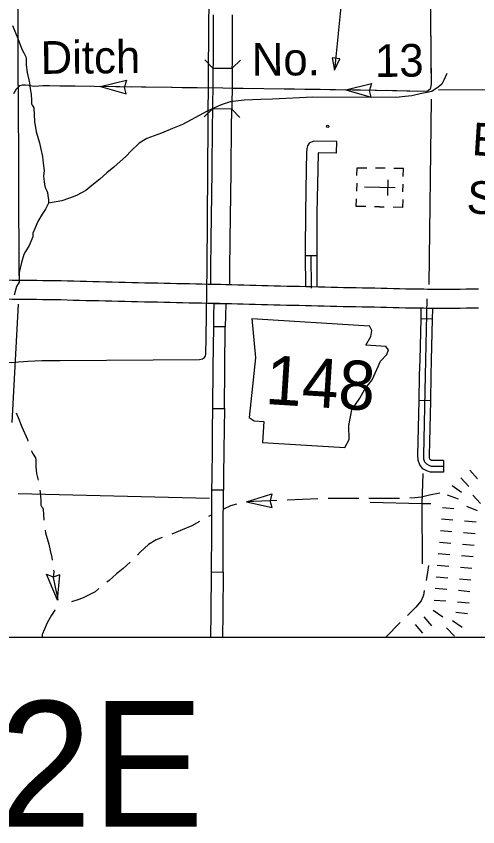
# Model space of a CAD drawing. Extents: x 1366406 to 1373462, y 376856 to 381998.
# Drawn here: x 1369525.2 to 1369621.8, y 379441 to 379610.7 of the extents above; entities that cross this region are included whole.
import ezdxf

# ---------------------------------------------------------------- set-up
doc = ezdxf.new("R2010")
doc.units = 0
for name, color, linetype in [('10', 7, 'Continuous'), ('21', 7, 'Continuous'), ('29', 7, 'Continuous'), ('31', 7, 'Continuous'), ('32', 7, 'Continuous'), ('37', 7, 'Continuous'), ('4', 7, 'Continuous'), ('41', 7, 'Continuous'), ('43', 7, 'Continuous'), ('45', 7, 'Continuous'), ('46', 7, 'Continuous'), ('5', 7, 'Continuous'), ('57', 7, 'Continuous'), ('Default', 7, 'Continuous'), ('R_No Plot', 7, 'Continuous')]:
    doc.layers.add(name, color=color, linetype=linetype)

msp = doc.modelspace()

# ---------------------------------------------------------------- linework, layer by layer
at = {"layer": '10'}
for points in [[(1369566.45, 379610.97), (1369566.45, 379609.71), (1369566.45, 379608.44), (1369566.44, 379607.16), (1369566.44, 379605.88), (1369566.43, 379604.6), (1369566.43, 379603.33), (1369566.43, 379602.06), (1369566.42, 379600.81), (1369566.41, 379599.82), (1369570.46, 379599.78)], [(1369570.46, 379599.78), (1369570.47, 379600.78), (1369570.48, 379602.05), (1369570.48, 379603.32), (1369570.48, 379604.59), (1369570.49, 379605.87), (1369570.49, 379607.15), (1369570.5, 379608.42), (1369570.5, 379609.69), (1369570.5, 379610.97)], [(1369566.41, 379599.82), (1369566.4, 379598.32), (1369566.38, 379597.09)], [(1369570.46, 379599.78), (1369570.43, 379597.05)], [(1369566.38, 379597.09), (1369566.37, 379595.87), (1369566.36, 379594.67), (1369566.34, 379593.47), (1369566.32, 379592.27), (1369566.31, 379591.28)], [(1369570.43, 379597.05), (1369570.42, 379595.83), (1369570.41, 379594.61), (1369570.39, 379593.41), (1369570.37, 379592.21), (1369570.36, 379591.21)], [(1369566.31, 379591.28), (1369566.3, 379591.07), (1369566.28, 379589.85), (1369566.27, 379588.63), (1369566.26, 379587.41), (1369566.25, 379586.19), (1369566.23, 379584.96), (1369566.21, 379583.72), (1369566.2, 379582.47), (1369566.19, 379581.23), (1369566.18, 379579.99), (1369566.16, 379578.76), (1369566.15, 379577.53), (1369566.14, 379576.33), (1369566.13, 379575.14), (1369566.11, 379573.96), (1369566.1, 379572.79), (1369566.08, 379571.61), (1369566.06, 379570.43), (1369566.04, 379569.25), (1369566.02, 379568.07), (1369566, 379566.89), (1369565.98, 379565.72), (1369565.97, 379564.57), (1369565.96, 379563.44), (1369565.95, 379562.33), (1369565.93, 379561.24), (1369565.92, 379560.18), (1369565.87, 379554.59), (1369569.92, 379554.5)], [(1369569.92, 379554.5), (1369569.97, 379560.14), (1369569.98, 379561.19), (1369570, 379562.28), (1369570, 379563.39), (1369570.02, 379564.52), (1369570.03, 379565.67), (1369570.05, 379566.83), (1369570.07, 379568), (1369570.09, 379569.18), (1369570.11, 379570.37), (1369570.13, 379571.55), (1369570.15, 379572.73), (1369570.16, 379573.91), (1369570.18, 379575.09), (1369570.19, 379576.29), (1369570.2, 379577.49), (1369570.21, 379578.72), (1369570.23, 379579.95), (1369570.24, 379581.2), (1369570.25, 379582.43), (1369570.26, 379583.66), (1369570.28, 379584.9), (1369570.3, 379586.13), (1369570.31, 379587.37), (1369570.32, 379588.6), (1369570.33, 379589.81), (1369570.35, 379591.01), (1369570.36, 379591.21), (1369566.31, 379591.28)], [(1369533.29, 379551.28), (1369532, 379551.3), (1369530.73, 379551.32), (1369529.45, 379551.33), (1369528.18, 379551.35), (1369526.9, 379551.36), (1369525.61, 379551.37), (1369524.33, 379551.39), (1369523.06, 379551.4), (1369521.78, 379551.41), (1369520.49, 379551.43), (1369520.44, 379551.43), (1369520.56, 379555.48)], [(1369520.53, 379555.48), (1369520.56, 379555.48), (1369521.82, 379555.46), (1369523.09, 379555.45), (1369524.38, 379555.44), (1369525.66, 379555.42), (1369526.94, 379555.41), (1369528.22, 379555.4), (1369529.5, 379555.38), (1369530.79, 379555.37), (1369532.07, 379555.35), (1369533.35, 379555.33)], [(1369533.35, 379555.33), (1369534.65, 379555.31), (1369535.95, 379555.27), (1369537.25, 379555.24), (1369538.57, 379555.21), (1369539.9, 379555.17), (1369541.24, 379555.14), (1369542.59, 379555.12), (1369543.95, 379555.08), (1369545.32, 379555.05), (1369546.69, 379555.01), (1369548.05, 379554.97), (1369549.41, 379554.94), (1369550.78, 379554.91), (1369552.14, 379554.88), (1369553.5, 379554.86), (1369554.86, 379554.83), (1369556.2, 379554.8), (1369557.54, 379554.77), (1369558.87, 379554.73), (1369560.19, 379554.71), (1369561.5, 379554.68), (1369562.8, 379554.65), (1369564.1, 379554.63), (1369565.37, 379554.6), (1369566.63, 379554.57), (1369567.84, 379554.55)], [(1369567.85, 379554.55), (1369568.05, 379554.54), (1369569.13, 379554.51), (1369570.38, 379554.48), (1369571.63, 379554.45), (1369572.88, 379554.42), (1369574.13, 379554.38), (1369575.38, 379554.35), (1369576.65, 379554.31), (1369577.93, 379554.28), (1369579.24, 379554.25), (1369580.56, 379554.22), (1369581.87, 379554.19), (1369583.19, 379554.17), (1369584.51, 379554.14), (1369585.84, 379554.12), (1369587.18, 379554.09), (1369588.51, 379554.05), (1369589.83, 379554.01), (1369591.15, 379553.97), (1369592.45, 379553.93), (1369593.76, 379553.9), (1369595.06, 379553.88), (1369596.37, 379553.86), (1369597.68, 379553.84), (1369599, 379553.82), (1369600.31, 379553.78), (1369601.61, 379553.75), (1369602.91, 379553.72), (1369604.21, 379553.69), (1369605.49, 379553.65), (1369606.76, 379553.63), (1369608.03, 379553.61), (1369609.29, 379553.58), (1369610.57, 379553.57), (1369611.3, 379553.54), (1369613.06, 379553.56), (1369614.34, 379553.55), (1369615.61, 379553.55), (1369616.89, 379553.56), (1369618.17, 379553.56), (1369619.45, 379553.57), (1369620.73, 379553.57), (1369622.01, 379553.58)], [(1369567.76, 379550.5), (1369566.54, 379550.52), (1369565.28, 379550.55), (1369564.01, 379550.58), (1369562.72, 379550.6), (1369561.42, 379550.63), (1369560.1, 379550.66), (1369558.77, 379550.69), (1369557.44, 379550.72), (1369556.11, 379550.75), (1369554.77, 379550.78), (1369553.42, 379550.81), (1369552.06, 379550.84), (1369550.69, 379550.86), (1369549.32, 379550.89), (1369547.95, 379550.92), (1369546.58, 379550.96), (1369545.21, 379551), (1369543.85, 379551.03), (1369542.5, 379551.07), (1369541.15, 379551.09), (1369539.8, 379551.12), (1369538.46, 379551.16), (1369537.15, 379551.19), (1369535.85, 379551.23), (1369534.57, 379551.26), (1369533.29, 379551.28)], [(1369622.02, 379549.53), (1369620.74, 379549.52), (1369619.47, 379549.52), (1369618.18, 379549.51), (1369616.9, 379549.51), (1369615.62, 379549.5), (1369614.34, 379549.5), (1369613.07, 379549.51), (1369611.25, 379549.49), (1369610.48, 379549.52), (1369609.23, 379549.53), (1369607.96, 379549.56), (1369606.68, 379549.58), (1369605.39, 379549.61), (1369604.1, 379549.64), (1369602.82, 379549.67), (1369601.52, 379549.7), (1369600.21, 379549.73), (1369598.91, 379549.77), (1369597.62, 379549.79), (1369596.31, 379549.81), (1369595, 379549.83), (1369593.68, 379549.85), (1369592.35, 379549.88), (1369591.03, 379549.92), (1369589.7, 379549.96), (1369588.39, 379550), (1369587.07, 379550.04), (1369585.76, 379550.07), (1369584.44, 379550.09), (1369583.12, 379550.12), (1369581.79, 379550.14), (1369580.46, 379550.17), (1369579.14, 379550.2), (1369577.84, 379550.23), (1369576.54, 379550.26), (1369575.27, 379550.3), (1369574.01, 379550.33), (1369572.76, 379550.37), (1369571.52, 379550.4), (1369570.28, 379550.44), (1369569.02, 379550.47), (1369567.94, 379550.49), (1369567.75, 379550.5)]]:
    msp.add_lwpolyline(points, dxfattribs=at)
at = {"layer": '21'}
for p, q in [((1369574.57, 379547.4), (1369575.29, 379539.12)), ((1369599.68, 379544.86), (1369599.17, 379545.84)), ((1369599.46, 379543.64), (1369599.68, 379544.86)), ((1369598.39, 379541.79), (1369599.46, 379543.64)), ((1369602.63, 379541.52), (1369598.39, 379541.79)), ((1369603.13, 379540.8), (1369602.63, 379541.52)), ((1369602.8, 379539.86), (1369603.13, 379540.8)), ((1369575.29, 379539.12), (1369573.96, 379526.7)), ((1369601.47, 379538.44), (1369602.8, 379539.86)), ((1369600.68, 379536.7), (1369601.47, 379538.44)), ((1369599.72, 379534.56), (1369600.68, 379536.7)), ((1369598.22, 379532.6), (1369599.72, 379534.56)), ((1369597.14, 379530.74), (1369598.22, 379532.6)), ((1369595.48, 379528.24), (1369597.14, 379530.74)), ((1369594.86, 379524.98), (1369595.48, 379528.24)), ((1369573.96, 379526.7), (1369575.01, 379525.95)), ((1369575.01, 379525.95), (1369577.06, 379525.82)), ((1369577.06, 379525.82), (1369576.79, 379521.45)), ((1369594.95, 379522.09), (1369594.86, 379524.98)), ((1369594.02, 379520.37), (1369594.95, 379522.09)), ((1369576.79, 379521.45), (1369594.02, 379520.37))]:
    msp.add_line(p, q, dxfattribs=at)
msp.add_lwpolyline([(1369574.57, 379547.4), (1369599.17, 379545.84)], dxfattribs=at)
at = {"layer": '29'}
for p, q in [((1369620.15, 379515.64), (1369621.77, 379513.83)), ((1369618.33, 379514.02), (1369619.95, 379512.21)), ((1369616.5, 379512.43), (1369618.47, 379511.01)), ((1369615.46, 379510.47), (1369617.76, 379509.67)), ((1369620.82, 379510.44), (1369622.44, 379508.63)), ((1369614.44, 379507.85), (1369616.86, 379507.65)), ((1369619.49, 379508.13), (1369621.74, 379507.22)), ((1369614.23, 379505.44), (1369616.65, 379505.23)), ((1369619.07, 379505.01), (1369621.49, 379504.8)), ((1369614.01, 379503.02), (1369616.44, 379502.81)), ((1369614.01, 379503.02), (1369616.44, 379502.81)), ((1369618.86, 379502.59), (1369621.28, 379502.38)), ((1369618.86, 379502.59), (1369621.28, 379502.38)), ((1369613.8, 379500.6), (1369616.22, 379500.39)), ((1369618.64, 379500.17), (1369621.06, 379499.96)), ((1369613.58, 379498.18), (1369616.01, 379497.97)), ((1369618.43, 379497.75), (1369620.85, 379497.54)), ((1369613.37, 379495.76), (1369615.79, 379495.55)), ((1369613.37, 379495.76), (1369615.79, 379495.55)), ((1369618.21, 379495.33), (1369620.63, 379495.12)), ((1369618.21, 379495.33), (1369620.63, 379495.12)), ((1369613.16, 379493.34), (1369615.58, 379493.13)), ((1369618, 379492.91), (1369620.42, 379492.7)), ((1369612.94, 379490.92), (1369615.36, 379490.71)), ((1369617.78, 379490.49), (1369620.2, 379490.28)), ((1369612.75, 379488.45), (1369615.18, 379488.27)), ((1369612.75, 379488.45), (1369615.18, 379488.27)), ((1369617.6, 379488.08), (1369620.02, 379487.9)), ((1369617.6, 379488.08), (1369620.02, 379487.9)), ((1369612.53, 379486.36), (1369614.51, 379484.94)), ((1369610.56, 379484.93), (1369612.13, 379483.08)), ((1369610.56, 379484.93), (1369612.13, 379483.08)), ((1369617.24, 379485.9), (1369619.66, 379485.62)), ((1369608.71, 379483.35), (1369610.29, 379481.5)), ((1369616.58, 379484.18), (1369618.55, 379482.76)), ((1369615.32, 379482.66), (1369616.98, 379480.89))]:
    msp.add_line(p, q, dxfattribs=at)
at = {"layer": '31'}
for p, q in [((1369568.99, 379545.64), (1369566.56, 379545.66)), ((1369566.38, 379528.56), (1369568.81, 379528.53)), ((1369568.63, 379511.43), (1369566.2, 379511.45)), ((1369566.2, 379511.45), (1369566.2, 379511.45)), ((1369566.08, 379494.34), (1369568.51, 379494.32))]:
    msp.add_line(p, q, dxfattribs=at)
for points in [[(1369518.7, 379539.94), (1369519.99, 379539.34), (1369521.22, 379538.81), (1369522.12, 379538.54), (1369522.97, 379538.26), (1369524.13, 379538.19), (1369525.72, 379538.32), (1369526.71, 379538.39), (1369527.68, 379538.45), (1369530.55, 379538.61), (1369534.4, 379538.6), (1369563.62, 379538.83), (1369564.22, 379538.94), (1369564.66, 379539.22), (1369564.83, 379539.54), (1369564.88, 379539.85), (1369564.96, 379543.36), (1369565.19, 379558.13), (1369565.46, 379598.16), (1369565.57, 379608.14), (1369565.83, 379631.95), (1369565.94, 379634.8), (1369566.02, 379636.5)], [(1369566.56, 379545.66), (1369566.58, 379548), (1369566.68, 379550.52), (1369569.11, 379550.46)], [(1369569.11, 379550.46), (1369569.01, 379547.94), (1369568.99, 379545.64)], [(1369566.47, 379537.11), (1369566.56, 379545.66)], [(1369568.9, 379537.09), (1369568.99, 379545.64)], [(1369566.38, 379528.56), (1369566.47, 379537.11)], [(1369568.81, 379528.53), (1369568.9, 379537.09)], [(1369566.28, 379520.01), (1369566.33, 379524.17), (1369566.38, 379528.56)], [(1369568.81, 379528.53), (1369568.76, 379524.14), (1369568.71, 379519.98)], [(1369566.2, 379511.45), (1369566.21, 379514.2), (1369566.28, 379520.01)], [(1369568.71, 379519.98), (1369568.64, 379514.17), (1369568.63, 379511.43)], [(1369566.14, 379502.89), (1369566.2, 379511.45)], [(1369568.57, 379502.88), (1369568.63, 379511.43)], [(1369566.08, 379494.34), (1369566.14, 379502.89)], [(1369568.51, 379494.32), (1369568.57, 379502.88)], [(1369566.02, 379485.79), (1369566.08, 379494.34)], [(1369568.51, 379494.32), (1369568.45, 379485.77)], [(1369565.99, 379480.59), (1369566.02, 379485.79)], [(1369568.45, 379485.77), (1369568.42, 379480.59)]]:
    msp.add_lwpolyline(points, dxfattribs=at)
at = {"layer": '32'}
msp.add_line((1369585.69, 379560.57), (1369588.12, 379560.59), dxfattribs=at)
for points in [[(1369585.69, 379560.57), (1369585.75, 379554.12)], [(1369586.9, 379560.58), (1369586.96, 379553.74)], [(1369588.12, 379560.59), (1369588.18, 379554.06)]]:
    msp.add_lwpolyline(points, dxfattribs=at)
at = {"layer": '37'}
for points in [[(1369566.41, 379599.82), (1369564.71, 379601.55)], [(1369572.19, 379601.48), (1369570.46, 379599.78)], [(1369564.56, 379589.59), (1369566.31, 379591.28)], [(1369570.36, 379591.21), (1369572.05, 379589.47)]]:
    msp.add_lwpolyline(points, dxfattribs=at)
at = {"layer": '4'}
msp.add_lwpolyline([(1369694.75, 379595.58), (1369613.62, 379595.17)], dxfattribs=at)
at = {"layer": '43'}
for p, q in [((1369542.88, 379595.92), (1369548.27, 379597.28)), ((1369548.27, 379597.28), (1369547.87, 379595.86)), ((1369594.2, 379595.22), (1369599.59, 379596.59)), ((1369599.59, 379596.59), (1369599.18, 379595.16)), ((1369542.88, 379595.92), (1369548.23, 379594.41)), ((1369548.23, 379594.41), (1369547.87, 379595.84)), ((1369594.2, 379595.22), (1369599.55, 379593.71)), ((1369599.55, 379593.71), (1369599.18, 379595.14)), ((1369573.4, 379509.02), (1369578.71, 379510.68)), ((1369578.72, 379510.68), (1369578.38, 379509.24)), ((1369573.4, 379509.02), (1369578.83, 379507.8)), ((1369578.81, 379507.8), (1369578.38, 379509.22)), ((1369531.55, 379493.85), (1369532.92, 379493.29)), ((1369533.87, 379488.41), (1369531.55, 379493.85)), ((1369534.36, 379493.75), (1369532.94, 379493.28)), ((1369533.87, 379488.41), (1369534.36, 379493.75))]:
    msp.add_line(p, q, dxfattribs=at)
for points in [[(1369611.82, 379623.49), (1369612.07, 379596.42), (1369611.86, 379595.38), (1369611.23, 379594.87), (1369600.35, 379595.14), (1369581.34, 379595.39), (1369568.49, 379595.57), (1369530.81, 379596.08), (1369529.85, 379596.02), (1369529.03, 379595.96), (1369528.53, 379596.03), (1369527.87, 379596.14), (1369527.14, 379596.22), (1369526.43, 379596.21), (1369525.98, 379596.08), (1369525.62, 379595.82), (1369525.24, 379595.36), (1369524.65, 379594.44)], [(1369524.44, 379608.69), (1369525.58, 379606), (1369525.97, 379604.86), (1369526.44, 379603.62), (1369526.82, 379603), (1369527.25, 379602.19), (1369527.32, 379601.74), (1369527.33, 379600.4), (1369527.5, 379598.91), (1369528, 379596.72), (1369528.16, 379595.47), (1369528.32, 379594.36), (1369528.39, 379593.12), (1369528.41, 379592.31), (1369528.54, 379592.05), (1369528.73, 379591.84), (1369528.88, 379591.45), (1369529.07, 379588.59), (1369529.36, 379586.49), (1369530.07, 379584.16), (1369530.37, 379582.82), (1369530.7, 379581.31), (1369530.84, 379579.89), (1369531.1, 379578.35), (1369530.95, 379577.19), (1369531.09, 379576.06), (1369531.11, 379575.46), (1369531.27, 379574.84), (1369531.61, 379574.14), (1369531.74, 379573.75), (1369531.82, 379573.12), (1369531.96, 379572.26), (1369531.97, 379571.54), (1369531.34, 379570.29), (1369530.66, 379569.25), (1369529.73, 379567.7), (1369529.2, 379566.34), (1369528.67, 379565.25), (1369528.69, 379564.46), (1369527.91, 379562.65), (1369527.19, 379561.41), (1369526.83, 379560.77), (1369526.31, 379559.08), (1369525.86, 379557.05), (1369525.82, 379555.56), (1369525.81, 379555.02), (1369525.29, 379554.09), (1369524.76, 379552.27)], [(1369611.95, 379609.59), (1369612.01, 379603.18)], [(1369612.03, 379601.04), (1369612.07, 379596.42), (1369611.86, 379595.38), (1369611.28, 379594.92)], [(1369615.39, 379598.64), (1369614.76, 379597.28), (1369614.29, 379596.44), (1369613.56, 379595.79), (1369612.22, 379594.89), (1369609.77, 379594.41), (1369608.07, 379594), (1369606.67, 379593.83), (1369605.41, 379593.73), (1369604.53, 379593.67), (1369587.29, 379593.69), (1369578.9, 379593.29), (1369576.42, 379593.21), (1369572.93, 379593.06), (1369570.04, 379592.77), (1369568.11, 379592.14), (1369566.59, 379591.44), (1369565.21, 379590.79), (1369561.81, 379588.98), (1369560.02, 379587.97), (1369557.96, 379587.14), (1369555.6, 379586.15), (1369552.53, 379585.05), (1369550.93, 379584.07), (1369549.19, 379582.44), (1369548.26, 379581.4), (1369545.67, 379579.03), (1369544.22, 379577.89), (1369542.7, 379576.55), (1369541.03, 379575.22), (1369539.8, 379574.17), (1369537.97, 379573.22), (1369537.13, 379572.84), (1369536.18, 379572.5), (1369534.74, 379572), (1369531.97, 379571.54)], [(1369532.19, 379596.06), (1369530.81, 379596.08), (1369529.85, 379596.02), (1369529.03, 379595.96), (1369528.53, 379596.03), (1369527.87, 379596.14), (1369527.14, 379596.22), (1369526.43, 379596.21), (1369525.98, 379596.08), (1369525.85, 379595.98)], [(1369537.53, 379595.99), (1369534.33, 379596.03)], [(1369540.74, 379595.95), (1369537.53, 379595.99)], [(1369549.29, 379595.83), (1369542.88, 379595.92)], [(1369557.85, 379595.71), (1369551.43, 379595.8)], [(1369566.37, 379595.6), (1369559.99, 379595.69)], [(1369574.95, 379595.48), (1369570.42, 379595.54)], [(1369583.51, 379595.36), (1369581.34, 379595.39), (1369577.09, 379595.45)], [(1369588.85, 379595.29), (1369585.64, 379595.33)], [(1369592.06, 379595.25), (1369588.85, 379595.29)], [(1369600.61, 379595.13), (1369600.35, 379595.14), (1369594.2, 379595.22)], [(1369609.16, 379594.92), (1369602.75, 379595.08)], [(1369525.24, 379527.63), (1369525.65, 379526.64), (1369526.41, 379524.71), (1369527.55, 379522.03), (1369527.66, 379521.7)], [(1369528.4, 379519.69), (1369528.41, 379519.64), (1369528.79, 379519.02), (1369529.23, 379518.21), (1369529.3, 379517.76), (1369529.3, 379516.42), (1369529.47, 379514.93), (1369529.79, 379513.54)], [(1369530.14, 379511.43), (1369530.29, 379510.38), (1369530.36, 379509.14), (1369530.38, 379508.33), (1369530.51, 379508.07), (1369530.7, 379507.86), (1369530.86, 379507.47), (1369531, 379505.17)], [(1369613.91, 379510.85), (1369611.74, 379510.43), (1369610.04, 379510.02), (1369608.64, 379509.85), (1369607.6, 379509.77)], [(1369571.31, 379508.56), (1369570.09, 379508.16), (1369568.6, 379507.48)], [(1369579.81, 379509.27), (1369578.39, 379509.23), (1369574.91, 379509.09), (1369573.41, 379508.93)], [(1369588.36, 379509.67), (1369581.95, 379509.36)], [(1369596.91, 379509.7), (1369590.49, 379509.71)], [(1369605.46, 379509.69), (1369599.05, 379509.7)], [(1369563.6, 379504.9), (1369561.99, 379503.99), (1369559.94, 379503.16), (1369557.77, 379502.25)], [(1369566.16, 379506.27), (1369565.48, 379505.91)], [(1369531.26, 379503.05), (1369531.33, 379502.51), (1369532.04, 379500.18), (1369532.34, 379498.84), (1369532.68, 379497.33), (1369532.73, 379496.82)], [(1369555.76, 379501.52), (1369554.5, 379501.07), (1369552.91, 379500.09), (1369551.16, 379498.46), (1369550.62, 379497.85)], [(1369549.08, 379496.36), (1369547.64, 379495.05), (1369546.19, 379493.91), (1369544.67, 379492.57), (1369544.2, 379492.2)], [(1369533.02, 379494.7), (1369533.07, 379494.37), (1369532.92, 379493.21), (1369533.58, 379490.16), (1369533.71, 379489.77), (1369533.79, 379489.14), (1369533.9, 379488.44)], [(1369611.55, 379495.68), (1369611.34, 379494.28), (1369611.02, 379492.52)], [(1369542.54, 379490.85), (1369541.77, 379490.19), (1369539.95, 379489.24), (1369539.11, 379488.86), (1369538.15, 379488.52), (1369536.82, 379488.06)], [(1369610.63, 379490.42), (1369610.46, 379489.46), (1369610.02, 379488.3), (1369608.88, 379487), (1369607.14, 379485.25)], [(1369533.38, 379486.44), (1369533.32, 379486.31), (1369532.63, 379485.27), (1369531.71, 379483.72), (1369531.7, 379483.71)], [(1369531.7, 379483.71), (1369531.17, 379482.36), (1369530.64, 379481.27), (1369530.65, 379480.72)], [(1369605.63, 379483.73), (1369602.51, 379480.59)]]:
    msp.add_lwpolyline(points, dxfattribs=at)
at = {"layer": '45'}
for p, q in [((1369612.39, 379547.25), (1369609.96, 379547.31)), ((1369611.99, 379530.15), (1369609.56, 379530.2)), ((1369614.68, 379517.65), (1369614.68, 379515.22))]:
    msp.add_line(p, q, dxfattribs=at)
for points in [[(1369614.68, 379516.44), (1369612.13, 379516.43), (1369611.68, 379516.59), (1369611.15, 379516.87), (1369610.77, 379517.35), (1369610.55, 379517.95), (1369610.52, 379518.79), (1369610.9, 379535.47), (1369611.28, 379551.52)], [(1369609.96, 379547.31), (1369610.01, 379549.52)], [(1369612.39, 379547.25), (1369612.44, 379549.51)], [(1369609.76, 379538.76), (1369609.96, 379547.31)], [(1369612.19, 379538.7), (1369612.39, 379547.25)], [(1369609.56, 379530.2), (1369609.68, 379535.5), (1369609.76, 379538.76)], [(1369611.99, 379530.15), (1369612.11, 379535.45), (1369612.19, 379538.7)], [(1369609.37, 379521.65), (1369609.56, 379530.2)], [(1369611.8, 379521.6), (1369611.99, 379530.15)], [(1369614.68, 379515.22), (1369611.93, 379515.22), (1369611.19, 379515.47), (1369610.36, 379515.92), (1369609.69, 379516.75), (1369609.35, 379517.72), (1369609.31, 379518.78), (1369609.37, 379521.65)], [(1369614.68, 379517.65), (1369612.33, 379517.65), (1369612.17, 379517.7), (1369611.95, 379517.82), (1369611.84, 379517.95), (1369611.76, 379518.19), (1369611.74, 379518.8), (1369611.8, 379521.6)]]:
    msp.add_lwpolyline(points, dxfattribs=at)
at = {"layer": '46'}
for points in [[(1369592.26, 379581.99), (1369592.33, 379584.42), (1369587.43, 379584.54), (1369586.58, 379584.1), (1369586.2, 379583.54), (1369586.03, 379582.99), (1369585.99, 379582.09), (1369585.93, 379578.64), (1369585.75, 379569.5), (1369585.73, 379561.77), (1369585.69, 379560.57)], [(1369592.26, 379581.99), (1369588.42, 379582.09), (1369588.42, 379582.02), (1369588.36, 379578.59), (1369588.18, 379569.47), (1369588.16, 379561.82), (1369588.12, 379560.59)]]:
    msp.add_lwpolyline(points, dxfattribs=at)
at = {"layer": '5'}
for points in [[(1369525.63, 379596.16), (1369525.66, 379639.07), (1369525.63, 379641.84)], [(1369525.63, 379596.16), (1369525.76, 379556.35)], [(1369612.06, 379593.32), (1369611.57, 379554.52)], [(1369525.62, 379550.39), (1369524.32, 379525.62)], [(1369610.34, 379514.93), (1369610.14, 379508.6)], [(1369565.65, 379509.69), (1369525.6, 379510.67)], [(1369610.14, 379508.6), (1369599.3, 379508.86)], [(1369612.01, 379508.59), (1369610.14, 379508.6)], [(1369610.14, 379508.6), (1369610.22, 379496.04)]]:
    msp.add_lwpolyline(points, dxfattribs=at)
at = {"layer": '57'}
for p, q in [((1369602.43, 379578.82), (1369600.4, 379578.86)), ((1369603, 379576.38), (1369602.93, 379573.13)), ((1369596.5, 379575.69), (1369596.47, 379574.07)), ((1369604.58, 379574.73), (1369598.11, 379574.86)), ((1369601.35, 379574.79), (1369601.35, 379574.79)), ((1369601.35, 379574.79), (1369601.35, 379574.79)), ((1369606.19, 379573.88), (1369606.22, 379575.5)), ((1369601.26, 379570.75), (1369600.24, 379570.77)), ((1369601.26, 379570.75), (1369602.26, 379570.73))]:
    msp.add_line(p, q, dxfattribs=at)
for points in [[(1369593.47, 379615.46), (1369591.83, 379599.35)], [(1369596.54, 379577.32), (1369596.57, 379578.94), (1369598.59, 379578.9)], [(1369606.25, 379577.13), (1369606.29, 379578.75), (1369604.26, 379578.79)], [(1369598.43, 379570.8), (1369596.4, 379570.84), (1369596.44, 379572.46)], [(1369606.16, 379572.27), (1369606.12, 379570.65), (1369604.1, 379570.69)]]:
    msp.add_lwpolyline(points, dxfattribs=at)
msp.add_lwpolyline([(1369592.97, 379601.71), (1369591.33, 379601.92), (1369591.83, 379599.35)], close=True, dxfattribs=at)
msp.add_circle((1369590.45, 379587.58), 0.243, dxfattribs=at)
at = {"layer": 'R_No Plot'}
msp.add_line((1369713.09, 379480.59), (1368990.63, 379480.59), dxfattribs=at)

# ---------------------------------------------------------------- texts
at = {"layer": '21'}
msp.add_text('148', height=10.264, rotation=356.4139, dxfattribs=at).set_placement((1369577.2, 379529.51))
at = {"layer": '41'}
for s, p in [('End', (1369620.49, 379581.6)), ('St. Hwy.', (1369619.38, 379569.47))]:
    msp.add_text(s, height=6.843, rotation=356.4139, dxfattribs=at).set_placement(p)
at = {"layer": '43'}
for s, p in [('Ditch', (1369530.35, 379598.58)), ('No.', (1369574.56, 379598.19)), ('13', (1369600.36, 379597.94))]:
    msp.add_text(s, height=6.843, rotation=0.5021, dxfattribs=at).set_placement(p)
at = {"layer": 'Default'}
msp.add_text('R12E', height=26.3, dxfattribs=at).set_placement((1369476.53, 379441))

doc.saveas('drawing.dxf')
